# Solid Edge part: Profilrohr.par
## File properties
Username: bmolnar
Dokumentum tartalom típus: 0
Author: bmolnar
Last saved by: bmolnar
Revision: 81
Sűrűség: 0,000 kg/m^3
Pontosság: 0,990
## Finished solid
Body 1: solid body, 91 faces, 266 edges, 176 vertices.
  Faces by surface: plane 46, cylinder 45
  Edges by curve: line 176, circle 90
Bounding box of the edges (mm): 49.000 x 49.000 x 45.800, from (-24.5, -24.5, 0) to (24.5, 24.5, 45.8).
Cylindrical faces by radius (mm): R0.15 x20, R0.25 x20, R8 x4, R16 x1
Planar faces by outward normal: +x 11, +y 11, +z 1, -x 11, -y 11, -z 1
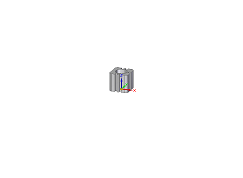
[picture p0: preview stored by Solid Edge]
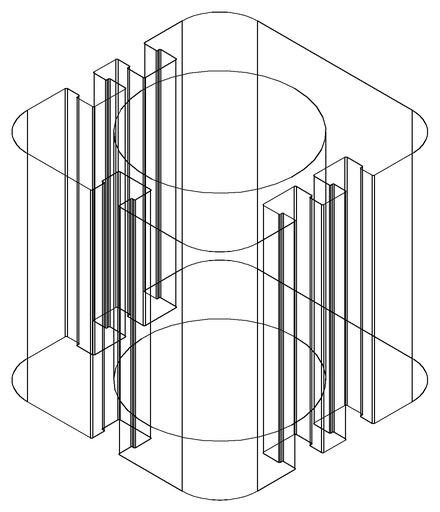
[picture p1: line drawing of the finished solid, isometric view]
